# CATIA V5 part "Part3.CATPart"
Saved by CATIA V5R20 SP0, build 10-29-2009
Part number: Part3
Bounding box of the stored display mesh (mm): x -250 to -79.373, y -20 to 20, z 300 to 320
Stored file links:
  C:\Users\Administrator\Downloads\Compressed\Animation-catia-farsi www.iranmeet.com\Animation-catia-farsi www.iranmeet.com\Samples www.iranmeet.com\Screw\Part3.CATPart
  C:\Users\Administrator\Downloads\Compressed\Animation-catia-farsi www.iranmeet.com\Animation-catia-farsi www.iranmeet.com\Samples www.iranmeet.com\Screw\Product1.CATProduct
  C:\Users\Administrator\Downloads\Compressed\Animation-catia-farsi www.iranmeet.com\Animation-catia-farsi www.iranmeet.com\Samples www.iranmeet.com\Screw\Part2.CATPart
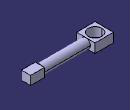
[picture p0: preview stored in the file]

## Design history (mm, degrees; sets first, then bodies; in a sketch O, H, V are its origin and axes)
Body1 (main body)
  DatumSurface1
  DatumCurve1
  Sketch1 on face of DatumSurface1, origin (0, 0, 300), H (1, 0, 0), V (0, 1, 0)
    line L1 (-110, -10) -> (-110, 10)
    arc A1 centre (0.006, 0) radius 80.006 from (-79.3726, 10) to (-79.3726, -10) ccw
    line L2 (-110, -10) -> (-79.3726, -10)
    line L3 (-110, 10) -> (-79.3726, 10)
    vertical: L1 V
    horizontal: L2 H, L3 H
  Pad1: profile Sketch1, direction (0, 0, 1), length 19
  DatumSurface2
  Sketch2 on face of Pad1 from Sketch1.L1, origin (-110, 0, 0), H (0, -1, 0), V (0, 0, 1)
    circle A1 centre (0, 310) radius 10
    point P1 (0, 310)
    point P2 (0, 320)
    coincidence: P1 V, A1 P2, P2 V
  Pad2: profile Sketch2, direction (-1, 0, 0), length 100
  Sketch3 on face of DatumSurface2, origin (0, 0, 350), H (1, 0, 0), V (0, 1, 0)
  DatumSurface3
  Plane1: type Offset, RefPlane DatumSurface3, Offset 30
  DatumCurve2
  Sketch4 on Plane1, origin (0, 0, 320), H (1, 0, 0), V (0, -1, 0)
    line L1 (-210, 20) -> (-250, 20)
    line L2 (-250, 20) -> (-250, -20)
    line L3 (-250, -20) -> (-210, -20)
    line L4 (-210, -20) -> (-210, 20)
    circle A1 centre (-229.994, 0) radius 15
    horizontal: L1 H, L3 H
    vertical: L2 V, L4 V
  Pad3: profile Sketch4, direction (0, 0, -1), length 20
  DatumCurve3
